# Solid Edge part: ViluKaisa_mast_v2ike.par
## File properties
Author: kaisa
Template: iso metric part.par
Last saved by: kaisa
Revision: 5
Application: Solid Edge
Density: 600.000 kg/m^3
Accuracy: 0.990
Username: kaisa
Material: Wood, Mahogany
Face Style: Copper
Fill Style: Wood (Radial)
Virtual Style: Wood (Radial)
Grouping: Non-metals\Woods
LibraryName: Materials
Coef. of Thermal Exp: 0.0
Thermal Conductivity: 0.0
Specific Heat: 0.0
Modulus of Elasticity: 0.0
Poisson's Ratio: 0.428
Yield Stress: 0.0
Ultimate Stress: 0.0
Elongation: 0.0
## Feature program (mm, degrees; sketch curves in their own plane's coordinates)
sketch for "unnamed RevolvedProtrusion 1" plane through (0, 0, 0) normal (1, 0, 0) x-axis (0, 1, 0)
  line (0, 0) -> (0, 200)
  line (0, 200) -> (3, 200)
  line (3, 200) -> (3, 0)
  line (3, 0) -> (0, 0)
revolve "unnamed RevolvedProtrusion 1" add finite 360 deg
sketch for "unnamed RevolvedProtrusion 2" plane through (-5, 0, 0) normal (1, 0, 0) x-axis (0, 1, 0)
  line (-75, 127.8222) -> (75, 127.8222)
  line (75, 126.4829) -> (75, 127.8222)
  line (-75, 126.4829) -> (75, 126.4829)
  line (-75, 127.8222) -> (-75, 126.4829)
revolve "unnamed RevolvedProtrusion 2" add finite 360 deg
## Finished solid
Body 1: solid body, 6 faces, 4 edges, 0 vertices, 2 separate solids.
  Faces by surface: plane 4, cylinder 2
  Edges by curve: circle 4
Bounding box of the edges (mm): 9.339 x 150.000 x 200.000, from (-6.3393, -75, 0) to (3, 75, 200).
Cylindrical faces by radius (mm): R1.3393 x1, R3 x1
Planar faces by outward normal: +y 1, +z 1, -y 1, -z 1
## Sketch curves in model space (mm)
line (-5, 75, 126.4829) -> (-5, 75, 127.8222)
line (-5, -75, 126.4829) -> (-5, 75, 126.4829)
line (-5, -75, 127.8222) -> (-5, -75, 126.4829)
line (-5, -75, 127.8222) -> (-5, 75, 127.8222)
line (0, 0, 200) -> (0, 3, 200)
line (0, 3, 200) -> (0, 3, 0)
line (0, 3, 0) -> (0, 0, 0)
line (0, 0, 0) -> (0, 0, 200)
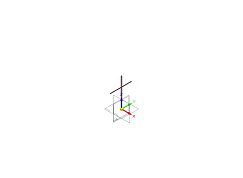
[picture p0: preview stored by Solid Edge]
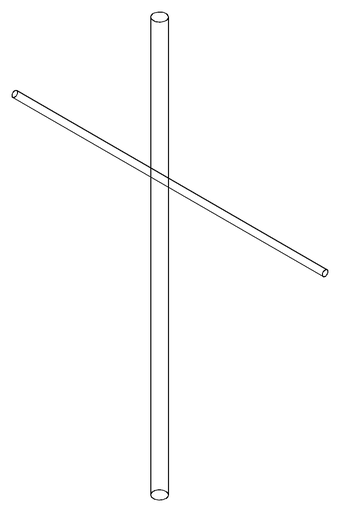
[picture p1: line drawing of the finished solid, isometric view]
